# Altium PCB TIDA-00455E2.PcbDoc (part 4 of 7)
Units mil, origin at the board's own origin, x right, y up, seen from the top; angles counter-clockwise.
Board outline 6693 x 6693.1 mil, 8 copper layers (Layer 1 - Top Layer, Layer 2 - GND, Layer 3 - Sensitive, Layer 4 - GND, Layer 5 - PWR, Layer 6 - Signal, Layer 7 - GND, Layer 8 - Bottom Layer), stack 63.122 mil thick; 537 components, 407 nets, 1686 pads, 1249 vias.
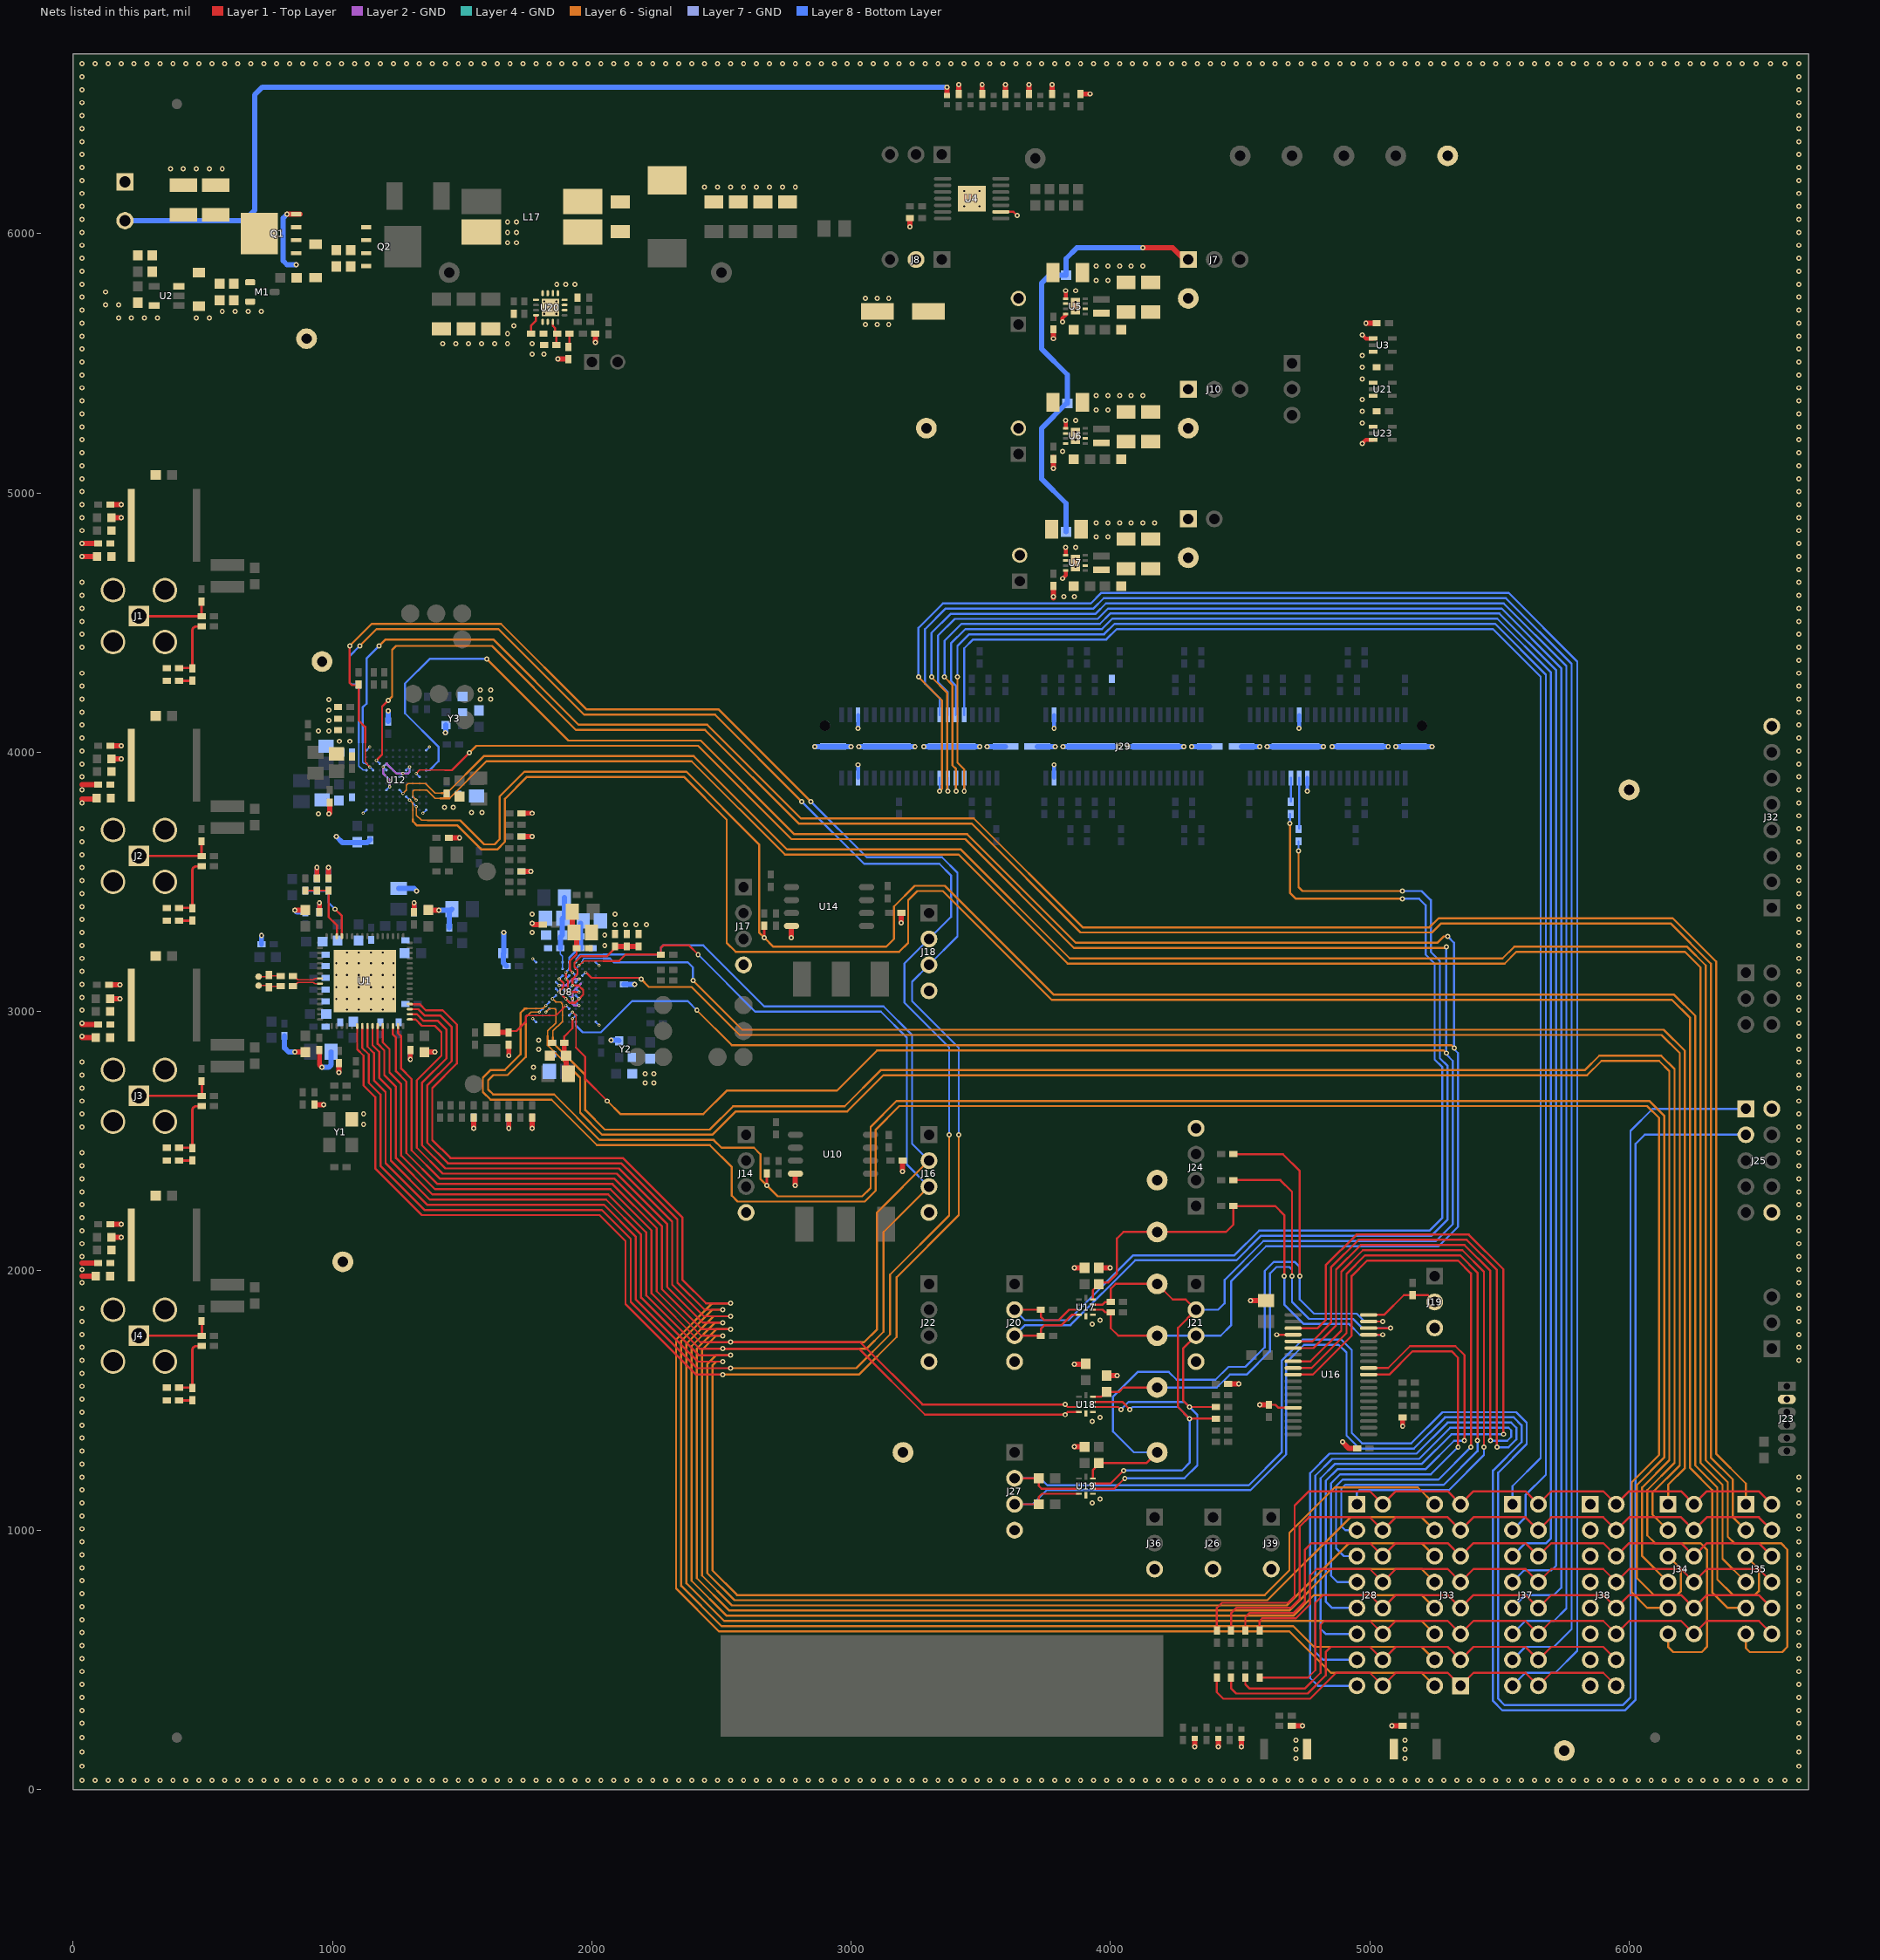
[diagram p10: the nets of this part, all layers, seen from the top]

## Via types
v1: diameter 20, hole 10, Layer 1 - Top Layer to Layer 8 - Bottom Layer, tented both sides, 1063 vias
v2: diameter 12, hole 6, Layer 1 - Top Layer to Layer 8 - Bottom Layer, tented bottom, 140 vias
v3: diameter 19.68, hole 7.87, Layer 1 - Top Layer to Layer 8 - Bottom Layer, 38 vias
v4: diameter 19.68, hole 7.87, Layer 1 - Top Layer to Layer 8 - Bottom Layer, tented top, 4 vias
v5: diameter 15.75, hole 7.87, Layer 1 - Top Layer to Layer 8 - Bottom Layer, 4 vias

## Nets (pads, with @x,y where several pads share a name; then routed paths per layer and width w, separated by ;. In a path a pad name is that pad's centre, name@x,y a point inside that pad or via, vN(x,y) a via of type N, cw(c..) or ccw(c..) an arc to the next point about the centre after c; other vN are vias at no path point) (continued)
GND: C1.2 C2.2 C3.2 C4.2 C5.2 C6.2 C7.2 C8.2 C15.2 C16.2 C17.2 C18.2 C19.2 C20.2 C21.2 C22.2 C30.1 C31.1 C32.2 C34.2 C35.2 C36.2 C37.2 C38.2 C39.2 C40.2 C41.2 C42.2 C43.2 C44.2 C45.2 C46.2 C47.2 C48.2 C49.2 C50.2 C51.2 C52.2 C53.2 C54.2 C56.2 C57.2 C58.2 C60.2 C61.2 C62.2 C63.2 C64.2 C65.2 C66.2 C69.2 C70.2 C71.2 C72.2 C75.2 C76.2 C77.2 C80.2 C84.2 C85.2 C86.2 C90.2 C91.2 C92.2 C94.2 C95.2 C96.2 C97.2 C100.2 C101.2 C102.2 C103.2 C106.2 C107.2 C108.2 C111.2 C112.2 C113.2 C114.2 C115.2 C116.2 C117.2 C118.1 C119.1 C120.1 C121.1 C122.1 C123.1 C124.1 C125.2 C126.2 C127.1 C128.2 C129.2 C130.2 C131.2 C132.1 C133.1 C134.2 C135.2 C136.2 C137.2 C138.1 C139.1 C140.1 C141.1 C142.1 C143.1 C144.1 C145.2 C146.2 C147.1 C148.2 C149.2 C150.2 C151.2 C152.1 C153.1 C154.2 C155.2 C156.2 C157.2 C158.2 C159.2 C160.1 C161.2 C162.1 C163.2 C164.2 D2.2 D4.2 D5.2 D12.1 J1.MH1 J1.MH2 J1.MH3 J1.MH4 J2.MH1 J2.MH2 J2.MH3 J2.MH4 J3.MH1 J3.MH2 J3.MH3 J3.MH4 J4.MH1 J4.MH2 J4.MH3 J4.MH4 J5.1 J14.4 J16.4 J17.4 J18.4 J19.3 J20.4 J21.4 J22.4 J23.2 J24.4 J25.2 J25.10 J26.3 J27.4 J29.26 J29.27 J29.77 J29.78 J29.115 J29.116 J29.MP1 J29.MP2 J29.MP3 J29.MP4 J29.MP5 J29.MP6 J29.MP7 J29.MP8 J29.MP9 J29.MP10 J29.MP11 J29.MP12 J32.8 J36.3 J38.1 J38.3 J38.5 J38.7 J38.9 J38.11 J38.13 J38.15 J39.3 L17.2 M1.2 R5.1 R6.1 R7.1 R8.1 R13.1 R14.1 R15.1 R16.1 R22.2 R23.1 R25.1 R28.1 R31.2 R38.1 R41.1 R44.1 R49.1 R50.1 R54.1 R55.1 R63.1 R68.1 R75.1 R76.1 R84.1 R85.1 R93.1 R98.1 R105.1 R106.1 R114.1 R115.1 R125.1 R127.2 R129.1 R130.2 R131.1 R132.1 R133.1 R134.1 R135.1 R137.1 R138.1 R140.1 R153.1 R155.1 R158.2 R161.2 R185.1 R201.1 R204.1 S1.2 S2.2 TP8.1 TP11.1 TP13.1 TP15.1 TP43.1 TP44.1 TP45.1 TP46.1 U1.65 U2.5 U3.1 U3.3 U4.2 U4.15 U5.1 U5.4 U5.9 U6.1 U6.4 U6.9 U7.1 U7.4 U7.9 U8.A1 U8.A10 U8.D4 U8.D7 U8.E5 U8.G7 U8.K1 U8.K10 U10.4 U12.A1 U12.A10 U12.D4 U12.D7 U12.E5 U12.G7 U12.K1 U12.K10 U14.4 U16.4 U16.15 U17.5 U17.6 U18.5 U18.6 U19.5 U19.6 U20.5 U20.6 U20.10 U20.11 U20.12 U20.13 U20.14 U20.17 U21.1 U21.3 U23.1 U23.3 Y1.2 Y2.2 Y2.4 Y3.2 Y3.4 | length 8429.3
  Layer 1 - Top Layer w8: U4.2@3577.2,6083.82 3626.18,6083.82 v1(3640,6070) ; C157.2@4610,1483.62 4636.38,1483.62 4647.95,1472.05 U16.15@4704.33,1472.05 ; v1(4641.46,1753.54) U16.4@4704.33,1753.54
  Layer 1 - Top Layer w15: v1(3815,4670) 3827.6,4682.6 U7.4@3827.6,4697.4 ; v1(3815,5660) 3815,5674.8 U5.4@3827.6,5687.4 ; U7.1@3827.6,4762.6 v1(3827.6,4790) ; U6.1@3827.6,5252.6 v1(3827.6,5280) ; U5.1@3827.6,5752.6 v1(3827.6,5780) ; v1(4970,5190) 4984.41,5204.41 U23.3@5012.6,5204.41 ; v1(4970,5610) 4984.41,5595.59 U3.1@5012.6,5595.59
  Layer 1 - Top Layer w20: 35,1980 C20.2@87.44,1980 ; 35,2030 C19.2@96.38,2030 ; v1@35,2900 C16.2@87.44,2900 ; v1@35,2950 C15.2@91.38,2950 ; 35,3820 87.45,3820 C6.2@90.24,3822.8 ; 35,3875 C5.2@96.38,3875 ; v1(35,4755) C2.2@92.44,4755 ; v1(35,4805) C1.2@96.38,4805 ; C17.2@138.62,3102.5 v1(180,3102.5) ; C18.2@142.56,3050 v1(180,3050) ; C21.2@143.62,2180 v1(185,2180) ; C7.2@143.62,4025 v1(185,4025) ; C3.2@143.62,4955 v1(185,4955) ; C22.2@147.56,2130 v1(185,2130) ; C8.2@147.56,3975 v1(185,3975) ; C4.2@147.56,4905 v1(185,4905) ; v1(855,2843.5) C84.2@895,2843.5 ; v1(855,3391.5) C70.2@895,3391.5 ; R155.1@930,2641.38 v1(966.38,2641.38) ; R49.1@940,3513.62 v1(940,3555) ; C85.2@950,2851.38 950,2795 v1(960,2785) ; C71.2@950,3383.62 v1(950,3420) ; C72.2@985,3513.62 v1(985,3555) ; v1(986.24,3762.5) 990,3766.26 R106.1@990,3806.38 ; v1(1025,2765) R54.1@1025,2801.38 ; v1(1300,2815) C108.2@1300,2851.38 ; C103.2@1315,3383.62 v1(1315,3420) ; C107.2@1355,2843.5 v1(1395,2843.5) ; C101.2@1370,3391.5 v1(1410,3391.5) ; C149.2@1448.62,3670 v1(1490,3670) ; v1(1545,2550) R134.1@1545,2591.38 ; v1(1680,2550) R85.1@1680,2591.38 ; v1(1680,2830) C129.2@1680,2871.38 ; R138.1@1728.62,3540 v1(1765,3540) ; R115.1@1728.62,3675 v1(1770,3675) ; R137.1@1728.62,3765 v1(1770,3765) ; v1(1770,2550) R133.1@1770,2591.38 ; v1(1770,3340) 1775,3335 R76.1@1811.38,3335 ; v1(1870,5516.38) C43.2@1910,5516.38 ; v1(2013.62,5580) R31.2@2013.62,5615 ; v1(2769.8,3285) 2769.8,3329.49 U14.4@2770.32,3330 ; v1(2784.8,2330) 2784.8,2374.49 U10.4@2785.31,2375 ; v1(3193.62,3341.38) R93.1@3193.62,3380 ; v1(3198.62,2383.62) R63.1@3198.62,2425 ; v1(3226.38,6026.38) R140.1@3226.38,6060 ; R50.1@3415,6538.62 v1(3415,6575) ; R125.1@3505,6538.62 v1(3505,6575) ; R127.2@3595,6538.62 v1(3595,6575) ; R132.1@3685,6538.62 v1(3685,6575) ; R131.1@3775,6538.62 v1(3775,6575) ; v1@3780,4595 v1(3780,4600) R204.1@3780,4641.38 R204.1@3780,4646.38 ; v1(3780,5095) R201.1@3780,5131.38 R201.1@3780,5136.38 ; v1(3780,5595) R129.1@3780,5631.38 R129.1@3780,5636.38 ; v1(3860,1321.5) C159.2@3900,1321.5 ; v1(3860,1640) 3903.5,1640 C158.2@3905,1641.5 ; v1(3860,2011.5) C161.2@3900,2011.5 ; R130.2@3885,6538.62 v1(3921.38,6538.62) ; R135.1@3955,2011.5 v1(3998.5,2011.5) ; R153.1@3985,1596.5 v1(4025,1596.5) ; v1(4325,165) D4.2@4325,197.28 ; v1(4415,165) D5.2@4415,197.28 ; R158.2@4453.62,1565 v1(4495,1565) ; v1(4505,165) D12.1@4505,197.28 ; v1(4540,1885) C156.2@4600,1885 ; v1(4575,1483.62) C157.2@4610,1483.62 ; C155.2@4698.62,245 v1(4740,245) ; v1(4895,1340) 4920,1315 R185.1@4951.38,1315 ; v1(4985,5655) C75.2@5026.38,5655 ; v1(5085,245) C80.2@5126.38,245 ; v1(5126.38,1401.38) R161.2@5126.38,1435
  Layer 2 - GND w8: v2(1195.06,3943.68) 1195.06,3918.94 1220.65,3893.35 v2(1220.65,3866.91) ; 1208.52,3956.48 1246.91,3918.09 v2(1271.83,3918.09) 1291.09,3918.09 1297.42,3924.42 v2(1297.42,3943.68) ; v2(1874.41,3100.59) 1900,3100.59 1925.59,3126.18 v2(1951.18,3126.18) ; v2(1951.18,3023.82) 1931.92,3023.82 1925.59,3030.15 v2(1925.59,3049.41) 1925.59,3075.33 1958.5,3108.24
  Layer 7 - GND w8: 1207.85,3956.48 v2(1195.06,3943.68) 1195.06,3918.94 1220.65,3893.35 v2(1220.65,3866.91) ; 1208.52,3956.48 1246.91,3918.09 v2(1271.83,3918.09) 1291.09,3918.09 1297.42,3924.42 v2(1297.42,3943.68) ; v2(1874.41,3100.59) 1900,3100.59 1925.59,3126.18 v2(1951.18,3126.18) v2@1953.82,3126.18 ; v2(1951.18,3023.82) 1931.92,3023.82 1925.59,3030.15 v2(1925.59,3049.41) 1925.59,3075.33 1958.5,3108.24
  Layer 4 - GND w8: v2(1195.06,3943.68) 1195.06,3918.94 1220.65,3893.35 v2(1220.65,3866.91) ; 1208.52,3956.48 1246.91,3918.09 v2(1271.83,3918.09) 1291.09,3918.09 1297.42,3924.42 v2(1297.42,3943.68) ; v2(1874.41,3100.59) 1900,3100.59 1925.59,3126.18 v2(1951.18,3126.18) ; v2(1951.18,3023.82) 1931.92,3023.82 1925.59,3030.15 v2(1925.59,3049.41) 1925.59,3075.33 1958.5,3108.24
  Layer 8 - Bottom Layer w5: v2(1118.29,3764.55) U12.K10@1131.08,3777.34 ; U12.A10@1131.08,4007.66 v2(1143.88,4020.45) ; v2(1195.06,3943.68) U12.D7@1207.85,3930.89 ; U12.G7@1207.85,3854.11 v2(1220.65,3866.91) ; U12.E5@1259.04,3905.3 v2(1271.83,3918.09) ; U12.D4@1284.63,3930.89 v2(1297.42,3943.68) ; v2(1348.6,3764.55) U12.K1@1361.4,3777.34 ; U12.A1@1361.4,4007.66 v2(1374.19,4020.45) ; v2(1772.05,2972.64) U8.K1@1784.84,2959.84 ; v2(1772.05,3202.95) U8.K10@1784.84,3190.16 ; U8.G7@1861.61,3113.39 v2(1874.41,3100.59) ; U8.E5@1912.8,3062.2 v2(1925.59,3049.41) ; U8.D4@1938.39,3036.61 v2(1951.18,3023.82) ; U8.D7@1938.39,3113.39 v2(1951.18,3126.18) ; U8.A1@2015.16,2959.84 v2(2027.95,2947.05) ; U8.A10@2015.16,3190.16 v2(2027.95,3177.36)
  Layer 8 - Bottom Layer w15: J29.116@3026.56,3900.89 v1(3026.56,3951.77) ; v1(3026.56,4092.91) J29.115@3026.56,4143.8 ; J29.78@3782.47,3900.89 v1(3782.47,3951.77) ; v1(3782.47,4092.91) J29.77@3782.47,4143.8 ; v1(4727.35,4092.91) J29.27@4727.35,4143.8 ; v1(4758.85,3850) J29.26@4758.85,3900.89
  Layer 8 - Bottom Layer w20: C111.2@726.38,3260 v1(726.38,3293.62) ; C61.2@815,2906.38 815,2860 831.5,2843.5 v1(855,2843.5) ; v1(855,3391.5) 862.87,3383.62 C69.2@895,3383.62 ; R55.1@940,3513.62 v1(940,3555) ; C77.2@950,3383.62 v1(950,3420) ; v1(960,2785) 985,2785 995,2795 C60.2@995,2845 ; C86.2@985,3513.62 v1(985,3555) ; v1(1015,3675) 1039,3651 1133.37,3651 C151.2@1146.24,3663.88 ; R98.1@1215,4118.62 v1(1215,4160) ; C92.2@1255,3475 1315,3475 v1(1325,3465) ; v1(1300,2815) C106.2@1300,2851.38 ; C100.2@1315,3383.62 v1(1315,3420) ; v1(1410,3391.5) C54.2@1456.5,3391.5 ; v1(1435,4075) 1437.52,4077.52 Y3.4@1437.52,4105.39 ; C56.2@1450,3323.62 1450,3385 C54.2@1456.5,3391.5 ; C54.2@1460,3395 C54.2@1456.5,3391.5 ; v1(1545,2550) R75.1@1545,2591.38 ; v1(1660,3305) 1660,3226.5 C132.1@1658.5,3225 1658.5,3187.87 C131.2@1671.38,3175 ; v1(1680,2550) R84.1@1680,2591.38 ; R105.1@1728.62,3540 v1(1765,3540) ; R114.1@1728.62,3675 v1(1770,3675) ; v1(2075,2890) 2102.87,2890 Y2.4@2105.39,2887.48 ; R68.1@2123.62,3105 v1(2165,3105) ; v1(2860,4022.15) J29.MP12@2930.5,4022.15 v1(3000,4022.15) ; v1(3030,4022.15) J29.MP11@3137.98,4022.15 v1(3245.96,4022.15) ; v1(3280,4022.15) J29.MP10@3387.98,4022.15 v1(3495.96,4022.15) ; v1(3524.96,4022.15) J29.MP9@3595.46,4022.15 ; J29.MP8@3717.9,4022.15 v1(3787.4,4022.15) ; v1(3817.4,4022.15) J29.MP7@3925.38,4022.15 v1(4033.36,4022.15) ; v1(4067.4,4022.15) J29.MP6@4175.38,4022.15 v1(4283.36,4022.15) ; v1(4312.36,4022.15) J29.MP5@4382.86,4022.15 ; J29.MP4@4505.3,4022.15 v1(4574.8,4022.15) ; v1(4604.8,4022.15) J29.MP3@4712.78,4022.15 v1(4820.77,4022.15) ; v1(4854.8,4022.15) J29.MP2@4962.78,4022.15 v1(5070.77,4022.15) ; v1(5099.76,4022.15) J29.MP1@5170.26,4022.15 v1(5239.76,4022.15)
  other v1: 35,35 85,35 135,35 185,35 235,35 285,35 335,35 385,35 435,35 485,35 535,35 585,35 635,35 685,35 735,35 785,35 835,35 885,35 935,35 985,35 1035,35 1085,35 1135,35 1185,35 1235,35 1285,35 1335,35 1385,35 1435,35 1485,35 1535,35 1585,35 1635,35 1685,35 1735,35 1785,35 1835,35 1885,35 1935,35 1985,35 2035,35 2085,35 2135,35 2185,35 2235,35 2285,35 2335,35 2385,35 2435,35 2485,35 2535,35 2585,35 2635,35 2685,35 2735,35 2785,35 2835,35 2885,35 2935,35 2985,35 3035,35 3085,35 3135,35 3185,35 3235,35 3285,35 3335,35 3385,35 3435,35 3485,35 3535,35 3585,35 3635,35 3685,35 3735,35 3785,35 3835,35 3885,35 3935,35 3985,35 4035,35 4085,35 4135,35 4185,35 4235,35 4285,35 4335,35 4385,35 4435,35 4485,35 4535,35 4585,35 4635,35 4685,35 4735,35 4785,35 4835,35 4885,35 4935,35 4985,35 5035,35 5085,35 5135,35 5185,35 5235,35 5285,35 5335,35 5385,35 5435,35 5485,35 5535,35 5585,35 5635,35 5685,35 5735,35 5785,35 5835,35 5885,35 5935,35 5985,35 6035,35 6085,35 6135,35 6185,35 6235,35 6285,35 6335,35 6385,35 6435,35 6490,35 6545,35 6600,35 6655,35 35,90 6655,90 4715,120 5135,120 35,145 6655,145 4715,155 5135,155 4715,190 5135,190 35,200 6655,200 35,255 6655,255 35,305 6655,305 35,355 6655,355 35,405 6655,405 35,455 6655,455 35,505 6655,505 35,555 6655,555 35,605 6655,605 35,655 6655,655 35,705 6655,705 35,755 6655,755 35,805 6655,805 35,855 6655,855 35,905 6655,905 35,955 6655,955 35,1005 6655,1005 35,1055 6655,1055 35,1105 3930,1105 6655,1105 3960,1120 35,1155 6655,1155 35,1205 6655,1205 35,1255 35,1305 35,1355 35,1405 3930,1420 3960,1435 35,1455 35,1505 35,1555 35,1605 35,1655 6655,1655 35,1705 6655,1705 35,1755 6655,1755 3930,1795 35,1805 6655,1805 3960,1810 35,1855 6655,1855 6655,1905 35,1955 6655,1955 35,2005 6655,2005 35,2055 6655,2055 35,2105 6655,2105 35,2155 6655,2155 35,2205 6655,2205 35,2255 6655,2255 35,2305 6655,2305 35,2355 6655,2355 35,2405 6655,2405 35,2455 6655,2455 6655,2505 35,2555 6655,2555 1120,2565 35,2605 1120,2605 6655,2605 35,2655 6655,2655 35,2705 6655,2705 2205,2725 2240,2725 1775,2745 35,2755 6655,2755 2205,2760 2240,2760 1775,2785 35,2805 6655,2805 1795,2855 6655,2855 1795,2890 35,2905 6655,2905 35,2955 6655,2955 35,3005 6655,3005 35,3055 6655,3055 35,3105 6655,3105 35,3155 6655,3155 35,3205 6655,3205 35,3255 2050,3255 6655,3255 2050,3295 35,3305 1770,3305 6655,3305 2090,3335 2130,3335 2170,3335 2210,3335 35,3355 6655,3355 1770,3375 2090,3375 35,3405 6655,3405 35,3455 6655,3455 35,3505 6655,3505 35,3555 6655,3555 35,3605 6655,3605 35,3655 6655,3655 35,3705 6655,3705 6655,3755 946.24,3762.5 1536.24,3767.5 1576.24,3767.5 1431.24,3787.5 1466.24,3787.5 35,3805 6655,3805 35,3855 6655,3855 35,3905 6655,3905 35,3955 6655,3955 35,4005 6655,4005 1026.24,4042.5 1066.24,4042.5 35,4055 6655,4055 946.24,4082.5 986.24,4082.5 35,4105 6655,4105 986.24,4122.5 35,4155 6655,4155 986.24,4162.5 986.24,4202.5 35,4205 1570,4205 1610,4205 6655,4205 1570,4240 1610,4240 35,4255 6655,4255 35,4305 6655,4305 6655,4355 35,4405 6655,4405 35,4455 6655,4455 35,4505 6655,4505 35,4555 6655,4555 3820,4600 3860,4600 35,4605 6655,4605 35,4655 6655,4655 6655,4705 6655,4755 3865,4790 6655,4805 3945,4830 3990,4830 35,4855 6655,4855 3945,4885 3990,4885 4035,4885 4080,4885 4125,4885 4170,4885 35,4905 6655,4905 35,4955 6655,4955 35,5005 6655,5005 35,5055 6655,5055 35,5105 6655,5105 35,5155 6655,5155 3815,5160 35,5205 6655,5205 35,5255 6655,5255 4970,5270 3865,5280 35,5305 6655,5305 4970,5315 3945,5320 3990,5320 35,5355 6655,5355 4970,5360 3945,5375 3990,5375 4035,5375 4080,5375 4125,5375 35,5405 6655,5405 4970,5440 35,5455 6655,5455 4970,5485 35,5505 6655,5505 4970,5530 1770,5535 1815,5535 35,5555 6655,5555 1425,5575 1475,5575 1525,5575 1575,5575 1625,5575 1675,5575 1770,5575 35,5605 6655,5605 1675,5615 1700,5645 3055,5650 3100,5650 3145,5650 35,5655 6655,5655 175,5675 225,5675 275,5675 325,5675 475,5675 525,5675 575,5700 625,5700 675,5700 725,5700 35,5705 6655,5705 125,5725 175,5725 3055,5750 3100,5750 3145,5750 35,5755 6655,5755 125,5775 3865,5780 35,5805 1865,5805 1900,5805 1935,5805 6655,5805 3945,5820 3990,5820 35,5855 6655,5855 3945,5875 3990,5875 4035,5875 4080,5875 4125,5875 35,5905 6655,5905 35,5955 6655,5955 1675,5965 1710,5965 35,6005 1675,6005 1710,6005 6655,6005 1675,6045 1710,6045 35,6055 6655,6055 35,6105 6655,6105 35,6155 6655,6155 2435,6180 2485,6180 2535,6180 2585,6180 2635,6180 2685,6180 2735,6180 2785,6180 35,6205 6655,6205 375,6250 425,6250 475,6250 525,6250 575,6250 35,6255 6655,6255 35,6305 6655,6305 35,6355 6655,6355 35,6405 6655,6405 35,6455 6655,6455 35,6505 6655,6505 35,6555 6655,6555 35,6605 6655,6605 35,6655 85,6655 135,6655 185,6655 235,6655 285,6655 335,6655 385,6655 435,6655 485,6655 535,6655 585,6655 635,6655 685,6655 735,6655 785,6655 835,6655 885,6655 935,6655 985,6655 1035,6655 1085,6655 1135,6655 1185,6655 1235,6655 1285,6655 1335,6655 1385,6655 1435,6655 1485,6655 1535,6655 1585,6655 1635,6655 1685,6655 1735,6655 1785,6655 1835,6655 1885,6655 1935,6655 1985,6655 2035,6655 2085,6655 2135,6655 2185,6655 2235,6655 2285,6655 2335,6655 2385,6655 2435,6655 2485,6655 2535,6655 2585,6655 2635,6655 2685,6655 2735,6655 2785,6655 2835,6655 2885,6655 2935,6655 2985,6655 3035,6655 3085,6655 3135,6655 3185,6655 3235,6655 3285,6655 3335,6655 3385,6655 3435,6655 3485,6655 3535,6655 3585,6655 3635,6655 3685,6655 3735,6655 3785,6655 3835,6655 3885,6655 3935,6655 3985,6655 4035,6655 4085,6655 4135,6655 4185,6655 4235,6655 4285,6655 4335,6655 4385,6655 4435,6655 4485,6655 4535,6655 4585,6655 4635,6655 4685,6655 4735,6655 4785,6655 4835,6655 4885,6655 4935,6655 4985,6655 5035,6655 5085,6655 5135,6655 5185,6655 5235,6655 5285,6655 5335,6655 5385,6655 5435,6655 5485,6655 5535,6655 5585,6655 5635,6655 5685,6655 5735,6655 5785,6655 5835,6655 5885,6655 5935,6655 5985,6655 6035,6655 6085,6655 6135,6655 6185,6655 6235,6655 6285,6655 6335,6655 6385,6655 6435,6655 6490,6655 6545,6655 6600,6655 6655,6655
  other v3: 1055.73,3007.28 1101.91,3007.28 1148.09,3007.28 1194.27,3007.28 1014.78,3048.23 1055.73,3048.23 1101.91,3048.23 1148.09,3048.23 1194.27,3048.23 1235.22,3048.23 1014.78,3094.41 1055.73,3094.41 1101.91,3094.41 1148.09,3094.41 1194.27,3094.41 1235.22,3094.41 1014.78,3140.59 1055.73,3140.59 1101.91,3140.59 1148.09,3140.59 1194.27,3140.59 1235.22,3140.59 1014.78,3186.77 1055.73,3186.77 1101.91,3186.77 1148.09,3186.77 1194.27,3186.77 1235.22,3186.77 1055.73,3227.72 1101.91,3227.72 1148.09,3227.72 1194.27,3227.72 3865,4714.25 3865,4745.75 3865,5204.25 3865,5235.75 3865,5704.25 3865,5735.75
  other v4: 1816.38,5691.38 1863.62,5691.38 1816.38,5738.62 1863.62,5738.62
  other v5: 3435.47,6105.47 3494.53,6105.47 3435.47,6164.53 3494.53,6164.53
GPIO0: J28.2 J33.15 J34.2 J35.2 J37.2 J38.2 R104.1 | length 2845.6
  Layer 1 - Top Layer w8: R104.1@4410,613.62 4410,700 4430,720 4685,720 4710,745 4710,1095 4765,1150 5000,1150 J28.2@5050,1100 5100,1150 5300,1150 J33.15@5350,1100 5400,1150 5600,1150 J37.2@5650,1100 5700,1150 5900,1150 J38.2@5950,1100 6000,1150 6200,1150 J34.2@6250,1100 6300,1150 6500,1150 J35.2@6550,1100
GPIO0_OV1: J34.1 U8.C10 | length 6214.6
  Layer 6 - Signal w8: v1(2390,3120) 2580,2930 6133.28,2930 6215,2848.28 6215,1240 6150,1175 J34.1@6150,1100
  Layer 8 - Bottom Layer w5: U8.C10@1963.98,3190.16 1963.98,3198.98 1970,3205 2045,3205
  Layer 8 - Bottom Layer w8: 2045,3205 2070,3205 2085,3190 2370,3190 2390,3170 v1(2390,3120)
GPIO0_OV2: J35.1 U12.C10 | length 8340.9
  Layer 6 - Signal w8: v1(1180,4410) 1205,4435 1620,4435 1949,4106 2445.27,4106 2806.27,3745 3472.99,3745 3892.99,3325 5230,3325 5265,3360 6168.28,3360 6335,3193.28 6335,1295 6450,1180 J35.1@6450,1100
  Layer 8 - Bottom Layer w5: 1116.24,4037.5 1116.24,3962.5 1122.26,3956.48 U12.C10@1131.08,3956.48
  Layer 8 - Bottom Layer w8: 1116.24,4037.5 1116.24,4172.5 1131.24,4187.5 1131.24,4361.24 v1(1180,4410)
GPIO0_SOC: J29.89 J37.1 | length 5823
  Layer 8 - Bottom Layer w8: J29.89@3436.01,4143.8 3436.01,4401.01 3470,4435 3983.68,4435 4023.68,4475 5475,4475 5658.73,4291.27 5658.73,1278.73 5550,1170 J37.1@5550,1100
GPIO0_UB960: J33.16 U1.9 | length 6261.8
  Layer 1 - Top Layer w8: U1.9@1134.84,2944.27 1134.84,2865.16 1160,2840 1160,2735 1205,2690 1205,2415 1365,2255 2046.57,2255 2170,2131.57 2170,1888.73 2408.73,1650 v1(2505,1650)
  Layer 6 - Signal w8: v1(2505,1650) 2480,1650 2465,1635 2465,845 2560,750 4595,750 4690,845 4690,990 4865,1165 5185,1165 J33.16@5250,1100
GPIO0_UC: J28.1 U16.8 | length 2382.2
  Layer 1 - Top Layer w8: U16.8@4704.33,1651.18 4771.18,1651.18 4890,1770 4890,1996.57 4973.43,2080 5356.57,2080 5440,1996.57 v1(5440,1320)
  Layer 8 - Bottom Layer w8: J28.1@4950,1100 4950,1145 4960,1155 5305,1155 5440,1290 v1(5440,1320)
GPIO1: J28.4 J33.13 J34.4 J35.4 J37.4 J38.4 R119.1 | length 2696.5
  Layer 1 - Top Layer w8: R119.1@4465,613.62 4465,680 4485,700 4695,700 4730,735 4730,1015 4765,1050 5000,1050 J28.4@5050,1000 5100,1050 5300,1050 J33.13@5350,1000 5400,1050 5600,1050 J37.4@5650,1000 5700,1050 5900,1050 J38.4@5950,1000 6000,1050 6200,1050 J34.4@6250,1000 6300,1050 6500,1050 J35.4@6550,1000
GPIO1_OV1: J34.3 U8.C8 | length 6273.8
  Layer 1 - Top Layer w8: v2(1976.77,3151.77) 1998.54,3130 2185,3130 v1(2190,3125)
  Layer 6 - Signal w8: v1(2190,3125) 2220,3095 2385,3095 2570,2910 6125,2910 6195,2840 6195,1250 6090,1145 6090,1060 J34.3@6150,1000
  Layer 8 - Bottom Layer w5: U8.C8@1963.98,3138.98 v2(1976.77,3151.77)
GPIO1_OV2: J35.3 U12.C8 | length 8337.4
  Layer 1 - Top Layer w8: v2(1169.47,3969.27) 1191.24,3991.04 1191.24,4176.24 v1(1215,4200)
  Layer 6 - Signal w8: v1(1215,4200) 1230,4215 1230,4395 1245,4410 1615,4410 1939,4086 2436.98,4086 2797.98,3725 3464.71,3725 3884.71,3305 5240,3305 5275,3340 6160,3340 6315,3185 6315,1280 6400,1195 6400,1050 J35.3@6450,1000
  Layer 8 - Bottom Layer w5: v2(1169.47,3969.27) U12.C8@1182.26,3956.48
GPIO1_SOC: J29.90 J37.3 | length 6359.4
  Layer 6 - Signal w8: v1(3410,4290) 3410,3960 3436.01,3933.99 v1(3436.01,3850)
  Layer 8 - Bottom Layer w8: v1(3410,4290) 3410,4410 3455,4455 3975.39,4455 4015.39,4495 5483.28,4495 5678.73,4299.56 5678.73,1213.73 5600,1135 5600,1050 J37.3@5550,1000 ; v1(3436.01,3850) J29.90@3436.01,3900.89
GPIO1_UB960: J33.14 U1.10 | length 6222.6
  Layer 1 - Top Layer w8: U1.10@1154.53,2944.27 1154.53,2870.47 1180,2845 1180,2745 1225,2700 1225,2425 1375,2275 2054.85,2275 2190,2139.85 2190,1897.01 2412.01,1675 v1(2535,1675)
  Layer 6 - Signal w8: v1(2535,1675) 2480,1675 2445,1640 2445,835 2550,730 4605,730 4925,1050 5200,1050 J33.14@5250,1000
GPIO1_UC: J28.3 U16.9 | length 2536.5
  Layer 1 - Top Layer w8: U16.9@4704.33,1625.59 4775.59,1625.59 4910,1760 4910,1988.28 4981.72,2060 5348.28,2060 5415,1993.28 v1(5415,1345)
  Layer 8 - Bottom Layer w8: J28.3@4950,1000 4905,1000 4890,1015 4890,1160 4905,1175 5285,1175 5415,1305 v1(5415,1345)
GPIO2: J28.6 J33.11 J34.6 J35.6 J37.6 J38.6 R120.1 | length 2544.4
  Layer 1 - Top Layer w8: R120.1@4520,613.62 4520,665 4535,680 4705,680 4750,725 4750,925 4775,950 5000,950 J28.6@5050,900 5100,950 5300,950 J33.11@5350,900 5400,950 5600,950 J37.6@5650,900 5700,950 5900,950 J38.6@5950,900 6000,950 6200,950 J34.6@6250,900 6300,950 6500,950 J35.6@6550,900
GPIO2_OV1: J34.5 R62.1 U8.J3 | length 7756.8
  Layer 1 - Top Layer w10: v1(2675,2330) R62.1@2675,2376.38
  Layer 6 - Signal w5: 1745,2955 1745,2978.23 1765,2998.23 v2(1797.64,2998.23)
  Layer 6 - Signal w8: 1745,2955 1745,2825 1675,2755 1620,2755 1600,2735 1600,2700 1620,2680 1855,2680 2030,2505 2470,2505 2500,2475 2625,2475 2650,2450 2650,2355 v1(2675,2330) 2717.5,2287.5 3042.5,2287.5 3075,2320 3075,2555 3175.5,2655.5 6077.78,2655.5 6135,2598.28 6135,1280 6030,1175 6030,815 6095,750 6185,750 6200,765 6200,850 J34.5@6150,900
  Layer 8 - Bottom Layer w5: v2(1797.64,2998.23) U8.J3@1810.43,3011.02
GPIO2_OV2: J35.5 R92.1 U12.J3 | length 8700.4
  Layer 1 - Top Layer w10: v1(2665.51,3285) R92.1@2665.51,3331.38
  Layer 6 - Signal w5: v2(1323.01,3790.14) 1323.01,3757.5 1343.01,3737.5 1366.24,3737.5
  Layer 6 - Signal w8: 1366.24,3737.5 1492.5,3737.5 1585,3645 1625,3645 1645,3665 1645,3830 1740,3925 2365,3925 2645,3645 2645,3305.51 v1(2665.51,3285) 2700.51,3250 3135,3250 3165,3280 3165,3405 3245,3485 3361.57,3485 3781.57,3065 6173.28,3065 6255,2983.28 6255,1250 6340,1165 6340,810 6400,750 6485,750 6500,765 6500,850 J35.5@6450,900
  Layer 8 - Bottom Layer w5: U12.J3@1310.22,3802.93 v2(1323.01,3790.14)
GPIO2_SOC: J29.91 J37.5 | length 6239.5
  Layer 8 - Bottom Layer w8: J29.91@3404.52,4143.8 3404.52,4255.48 3385,4275 3385,4420 3440,4475 3967.11,4475 4007.11,4515 5491.57,4515 5698.73,4307.84 5698.73,968.73 5680,950 5600,950 J37.5@5550,900
GPIO2_UB960: J33.12 U1.14 | length 6130.5
  Layer 1 - Top Layer w8: U1.14@1233.27,2944.27 1233.27,2911.73 1245,2900 1245,2770 1285,2730 1285,2455 1405,2335 2079.71,2335 2250,2164.71 2250,1921.86 2421.86,1750 v1(2505,1750)
  Layer 6 - Signal w8: v1(2505,1750) 2480,1750 2425,1695 2425,825 2540,710 4680,710 4920,950 5200,950 J33.12@5250,900
GPIO2_UC: J28.5 U16.10 | length 2607.9
  Layer 1 - Top Layer w8: U16.10@4704.33,1600 4780,1600 4930,1750 4930,1980 4990,2040 5340,2040 5390,1990 v1(5390,1320)
  Layer 8 - Bottom Layer w8: J28.5@4950,900 4900,900 4870,930 4870,1170 4895,1195 5265,1195 v1(5390,1320)
GPIO3: J28.8 J33.9 J34.8 J35.8 J37.8 J38.8 R144.1 | length 2386.5
  Layer 1 - Top Layer w8: R144.1@4575,613.62 4575,650 4585,660 4715,660 4770,715 4770,825 4795,850 5000,850 J28.8@5050,800 5100,850 5300,850 J33.9@5350,800 5400,850 5600,850 J37.8@5650,800 5700,850 5900,850 J38.8@5950,800 6000,850 6200,850 J34.8@6250,800 6300,850 6500,850 J35.8@6550,800
GPIO3_OV1: J34.7 U8.H3 | length 6949.7
  Layer 6 - Signal w5: v2(1823.23,2998.23) 1836.02,3011.02 1856.98,3011.02 1861.61,3006.39 1861.61,2956.61 1830,2925 1830,2905
  Layer 6 - Signal w8: 1830,2905 1830,2870 1955,2745 1955,2610 2040,2525 2465,2525 2555,2615 2985,2615 3124,2754 5837.28,2754 5893.28,2810 6115,2810 6155,2770 6155,1270 6050,1165 6050,900 J34.7@6150,800
  Layer 8 - Bottom Layer w5: v2(1823.23,2998.23) U8.H3@1836.02,3011.02
GPIO3_OV2: J35.7 U12.H3 | length 7905
  Layer 6 - Signal w5: v2(1323.01,3815.73) 1310.22,3828.52 1310.22,3849.48 1314.85,3854.11 1364.63,3854.11 1396.24,3822.5 1416.24,3822.5
  Layer 6 - Signal w8: 1416.24,3822.5 1451.24,3822.5 1593.74,3965 2385,3965 2745,3605 3415,3605 3835,3185 5520,3185 5565,3230 6215,3230 6275,3170 6275,1260 6360,1175 6360,890 J35.7@6450,800
  Layer 8 - Bottom Layer w5: U12.H3@1310.22,3828.52 v2(1323.01,3815.73)
GPIO3_SOC: J29.92 J37.7 | length 6789.7
  Layer 6 - Signal w8: v1(3360,4290) 3390,4260 3390,3950 3404.52,3935.48 v1(3404.52,3850)
  Layer 8 - Bottom Layer w8: v1(3360,4290) 3360,4430 3425,4495 3958.82,4495 3998.82,4535 5499.85,4535 5718.73,4316.12 5718.73,863.73 5700,845 5595,845 J37.7@5550,800 ; v1(3404.52,3850) J29.92@3404.52,3900.89
GPIO3_UB960: J33.10 U1.15 | length 6188.7
  Layer 1 - Top Layer w8: U1.15@1252.95,2944.27 1252.95,2917.05 1265,2905 1265,2780 1305,2740 1305,2465 1415,2355 2087.99,2355 2270,2172.99 2270,1930.15 2425.15,1775 v1(2535,1775)
  Layer 6 - Signal w8: v1(2535,1775) 2480,1775 2405,1700 2405,815 2530,690 4690,690 4850,850 5200,850 J33.10@5250,800
GPIO3_UC: J28.7 U16.29 | length 1750.3
  Layer 1 - Top Layer w8: U16.29@4995.67,1600 5075,1600 5165,1690 5315,1690 5340,1665 v1(5340,1320)
  Layer 8 - Bottom Layer w8: J28.7@4950,800 4875,800 4850,825 4850,1180 4885,1215 5235,1215 v1(5340,1320)
GPIO4: J28.10 J33.7 J34.10 J35.10 J37.10 J38.10 R146.1 | length 2487.1
  Layer 1 - Top Layer w8: R146.1@4575,431.38 4761.38,431.38 4790,460 4790,720 4820,750 5000,750 J28.10@5050,700 5100,750 5300,750 J33.7@5350,700 5400,750 5600,750 J37.10@5650,700 5700,750 5900,750 J38.10@5950,700 6000,750 6200,750 J34.10@6250,700 6300,750 6500,750 J35.10@6550,700
GPIO4_OV1: J34.9 U8.H4 | length 7647.3
  Layer 6 - Signal w5: 1750,3011.02 1810.43,3011.02 v2(1823.23,3023.82)
  Layer 6 - Signal w8: 1750,3011.02 1741.02,3011.02 1725,2995 1725,2835 1665,2775 1610,2775 1580,2745 1580,2690 1610,2660 1845,2660 2020,2485 2455,2485 2540,2400 2540,2290 2562.5,2267.5 3052.5,2267.5 3095,2310 3095,2545 3185.5,2635.5 6069.5,2635.5 6115,2590 6115,1290 6010,1185 6010,760 6070,700 J34.9@6150,700
  Layer 8 - Bottom Layer w5: v2(1823.23,3023.82) U8.H4@1836.02,3036.61
GPIO4_OV2: J35.9 U12.H4 | length 8647.8
  Layer 6 - Signal w5: v2(1297.42,3815.73) 1310.22,3802.93 1310.22,3742.5
  Layer 6 - Signal w8: 1310.22,3742.5 1310.22,3733.52 1326.24,3717.5 1482.5,3717.5 1575,3625 1635,3625 1665,3655 1665,3820 1750,3905 2355,3905 2520,3740 2520,3265 2555,3230 3185,3230 3220,3265 3220,3430 3255,3465 3353.28,3465 3773.28,3045 6165,3045 6235,2975 6235,1240 6320,1155 6320,760 6380,700 J35.9@6450,700
  Layer 8 - Bottom Layer w5: U12.H4@1284.63,3828.52 v2(1297.42,3815.73)
GPIO4_SOC: J29.93 J37.9 | length 6629.9
  Layer 8 - Bottom Layer w8: J29.93@3373.02,4143.8 3373.02,4231.98 3335,4270 3335,4450 3399.27,4514.27 3950.84,4514.27 3990.84,4554.27 5507.84,4554.27 5738,4324.11 5738,778 5710,750 5600,750 J37.9@5550,700
GPIO4_UB960: J33.8 U1.17 | length 6265.7
  Layer 1 - Top Layer w8: U1.17@1298.23,2969.86 1320.14,2969.86 1345,2945 1395,2945 1420,2920 1420,2830 1325,2735 1325,2475 1425,2375 2096.27,2375 2290,2181.27 2290,1938.43 2428.43,1800 v1(2505,1800)
  Layer 6 - Signal w8: v1(2505,1800) 2475,1800 2385,1710 2385,805 2520,670 4705,670 4785,750 5200,750 J33.8@5250,700
GPIO4_UC: J28.9 U16.30 | length 1943.4
  Layer 1 - Top Layer w8: U16.30@4995.67,1625.59 5070.59,1625.59 5155,1710 5330,1710 5365,1675 v1(5365,1345)
  Layer 8 - Bottom Layer w8: J28.9@4950,700 4855,700 4830,725 4830,1190 4875,1235 5215,1235 5325,1345 v1(5365,1345)
GPIO5: J28.12 J33.5 J34.12 J35.12 J37.12 J38.12 R148.1 | length 2506.5
  Layer 1 - Top Layer w8: R148.1@4520,431.38 4520,405 4535,390 4750,390 4810,450 4810,635 4825,650 5000,650 J28.12@5050,600 5100,650 5300,650 J33.5@5350,600 5400,650 5600,650 J37.12@5650,600 5700,650 5900,650 J38.12@5950,600 6000,650 6200,650 J34.12@6250,600 6300,650 6500,650 J35.12@6550,600
GPIO5_OV1: J34.11 U8.G5 | length 7597.4
  Layer 6 - Signal w5: v2(1848.82,3049.41) 1861.91,3036.32 1879.59,3036.32 1886.91,3029 1886.91,2961.91 1850,2925 1850,2900
  Layer 6 - Signal w8: 1850,2900 1850,2880 1975,2755 1975,2620 2050,2545 2455,2545 2545,2635 2975,2635 3114,2774 5829,2774 5885,2830 6123.28,2830 6175,2778.28 6175,1260 6070,1155 6070,980 6100,950 6275,950 6300,925 6300,550 6280,530 6170,530 6150,550 J34.11@6150,600
  Layer 8 - Bottom Layer w5: v2(1848.82,3049.41) U8.G5@1861.61,3062.2
GPIO5_OV2: J35.11 U12.G5 | length 8606.8
  Layer 6 - Signal w5: v2(1271.83,3841.32) 1284.92,3854.41 1284.92,3872.09 1292.24,3879.41 1359.33,3879.41 1396.24,3842.5 1421.24,3842.5
  Layer 6 - Signal w8: 1421.24,3842.5 1441.24,3842.5 1583.74,3985 2393.28,3985 2753.28,3625 3423.28,3625 3843.28,3205 5511.72,3205 5556.72,3250 6223.28,3250 6295,3178.28 6295,1270 6380,1185 6380,975 6405,950 6585,950 6610,925 6610,550 6590,530 6465,530 6450,545 J35.11@6450,600
  Layer 8 - Bottom Layer w5: U12.G5@1259.04,3854.11 v2(1271.83,3841.32)
GPIO5_SOC: J29.94 J37.11 | length 7165.5
  Layer 6 - Signal w8: v1(3310,4290) 3370,4230 3370,3853.02 v1(3373.02,3850)
  Layer 8 - Bottom Layer w8: v1(3310,4290) 3310,4460 3384.27,4534.27 3942.56,4534.27 3982.56,4574.27 5516.12,4574.27 5758,4332.39 5758,698 5710,650 5600,650 J37.11@5550,600 ; v1(3373.02,3850) J29.94@3373.02,3900.89
GPIO5_UB960: J33.6 U1.18 | length 6360.7
  Layer 1 - Top Layer w8: U1.18@1298.23,2989.55 1325.45,2989.55 1350,2965 1405,2965 1440,2930 1440,2820 1345,2725 1345,2485 1435,2395 2104.56,2395 2310,2189.56 2310,1946.72 2431.72,1825 v1(2535,1825)
  Layer 6 - Signal w8: v1(2535,1825) 2470,1825 2365,1720 2365,795 2510,650 5200,650 J33.6@5250,600
GPIO5_UC: J28.11 U16.3 | length 3279.4
  Layer 1 - Top Layer w8: U16.3@4704.33,1779.13 4799.13,1779.13 4830,1810 4830,2021.42 4948.58,2140 5381.42,2140 5515,2006.42 v1(5515,1370)
  Layer 8 - Bottom Layer w8: J28.11@4950,600 4830,600 4810,620 4810,1200 4865,1255 5200,1255 5315,1370 v1(5515,1370)
GPIO6: J28.14 J33.3 J37.14 J38.14 R149.1 | length 1806.9
  Layer 1 - Top Layer w8: R149.1@4465,431.38 4465,390 4485,370 4760,370 4830,440 4830,530 4850,550 5000,550 J28.14@5050,500 5100,550 5300,550 J33.3@5350,500 5400,550 5600,550 J37.14@5650,500 5700,550 5900,550 J38.14@5950,500
GPIO6_SOC: J29.95 J37.13 | length 7001.6
  Layer 8 - Bottom Layer w8: J29.95@3341.52,4143.8 3341.52,4208.48 3285,4265 3285,4475 3364.27,4554.27 3934.27,4554.27 3974.27,4594.27 5524.4,4594.27 5778,4340.68 5778,618 5710,550 5600,550 J37.13@5550,500
GPIO6_UB960: J33.4 U1.19 | length 6402
  Layer 1 - Top Layer w8: U1.19@1298.23,3009.23 1330.77,3009.23 1355,2985 1415,2985 1460,2940 1460,2810 1365,2715 1365,2495 1445,2415 2112.84,2415 2330,2197.84 2330,1955 2435,1850 v1(2505,1850)
  Layer 6 - Signal w8: v1(2505,1850) 2465,1850 2345,1730 2345,785 2500,630 4705,630 4785,550 5200,550 J33.4@5250,500
GPIO6_UC: J28.13 U16.6 | length 3547
  Layer 1 - Top Layer w8: U16.6@4704.33,1702.36 4782.36,1702.36 4870,1790 4870,2004.85 4965.15,2100 5364.85,2100 5465,1999.85 v1(5465,1345)
  Layer 8 - Bottom Layer w8: J28.13@4950,500 4820,500 4790,530 4790,1210 4855,1275 5190,1275 5310,1395 5535,1395 5545,1385 5545,1360 5530,1345 v1(5465,1345)
GPIO7: J28.16 J33.1 J37.16 J38.16 R150.1 | length 1793.1
  Layer 1 - Top Layer w8: R150.1@4410,431.38 4410,375 4435,350 4770,350 4870,450 5000,450 J28.16@5050,400 5100,450 5300,450 J33.1@5350,400 5400,450 5600,450 J37.16@5650,400 5700,450 5900,450 J38.16@5950,400
GPIO7_SOC: J29.96 J37.15 | length 7548.3
  Layer 6 - Signal w8: v1(3260,4290) 3350,4200 3350,3858.48 v1(3341.52,3850)
  Layer 8 - Bottom Layer w8: v1(3260,4290) 3260,4480 3353.54,4573.54 3923.54,4573.54 3965,4615 5535,4615 5800,4350 5800,535 5715,450 5600,450 J37.15@5550,400 ; v1(3341.52,3850) J29.96@3341.52,3900.89
GPIO7_UB960: J33.2 U1.20 | length 6558.7
  Layer 1 - Top Layer w8: U1.20@1298.23,3028.92 1336.08,3028.92 1360,3005 1425,3005 1480,2950 1480,2800 1385,2705 1385,2505 1455,2435 2120,2435 2350,2205 2350,1965 2440,1875 v1(2535,1875)
  Layer 6 - Signal w8: v1(2535,1875) 2465,1875 2325,1735 2325,775 2490,610 4690,610 4850,450 5200,450 J33.2@5250,400
GPIO7_UC: J28.15 U16.5 | length 3803.4
  Layer 1 - Top Layer w8: U16.5@4704.33,1727.95 4777.95,1727.95 4850,1800 4850,2013.14 4956.86,2120 5373.14,2120 5490,2003.14 v1(5490,1320)
  Layer 8 - Bottom Layer w8: J28.15@4950,400 4800,400 4770,430 4770,1220 4845,1295 5180,1295 5300,1415 5545,1415 5565,1395 5565,1350 5535,1320 v1(5490,1320)
HS_OPTION2: R202.1
I2C1_SCL: J29.30 R186.1 | length 91.4
  Layer 8 - Bottom Layer w8: R186.1@4695.86,3809.48 J29.30@4695.86,3900.89
I2C1_SDA: J29.28 R152.1 | length 194.9
  Layer 8 - Bottom Layer w8: R152.1@4727.35,3705.97 J29.28@4727.35,3900.89
I2C_SCL_EXT: J25.1 J27.2 R172.1 U19.3 | length 7436.5
  Layer 1 - Top Layer w8: J27.2@3630,1200 R172.1@3723.5,1200 3723.5,1170.5 3733.84,1160.16 U19.3@3878.43,1160.16
  Layer 8 - Bottom Layer w8: J27.2@3630,1200 3730,1200 3757.2,1172.8 4532.8,1172.8 4660,1300 4660,1653.72 4741.28,1735 4890,1735 4930.17,1694.83 4930.17,1374.83 4970,1335 5160,1335 5280,1455 5565,1455 5605,1415 5605,1331.72 5495,1221.72 5495,350 5520,325 5975.01,325 6005,354.99 6005,2540 6090,2625 J25.1@6450,2625
I2C_SCL_OV1: J16.2 R56.1 U1.12 U8.D10 U18.3 | length 7006.2
  Layer 1 - Top Layer w8: U1.12@1193.9,2944.27 1193.9,2881.1 1220,2855 1220,2765 1265,2720 1265,2445 1395,2315 2071.42,2315 2230,2156.42 2230,1913.58 2418.58,1725 v1(2535,1725) 3035,1725 3275,1485 v1(3825,1485) 3834.84,1475.16 U18.3@3878.43,1475.16
  Layer 6 - Signal w8: v1(2535,1725) 3050,1725 3100,1775 3100,2225 J16.2@3300,2425
  Layer 8 - Bottom Layer w5: U8.D10@1938.39,3190.16 1938.39,3203.39 1955,3220 2045,3220
  Layer 8 - Bottom Layer w8: 2045,3220 R56.1@2266.38,3220 2266.38,3246.38 2275,3255 2430,3255 2665,3020 3125,3020 3235,2910 3235,2490 J16.2@3300,2425
I2C_SCL_OV2: J18.2 R86.1 U1.8 U12.D10 | length 8305.2
  Layer 1 - Top Layer w8: U1.8@1115.16,2944.27 1115.16,2859.84 1140,2835 1140,2725 1185,2680 1185,2405 1355,2235 2038.28,2235 2150,2123.28 2150,1880.44 2405.44,1625 v1(2535,1625)
  Layer 6 - Signal w8: v1(1105,4410) 1170,4475 1640,4475 1970,4145 2475,4145 v1(2810,3810) ; v1(2535,1625) 3020,1625 3150,1755 3150,1985.36 3378,2213.36 v1(3378,2525)
  Layer 8 - Bottom Layer w5: 1101.24,4037.5 1101.24,3947.5 1117.85,3930.89 U12.D10@1131.08,3930.89
  Layer 8 - Bottom Layer w8: R86.1@1100,4261.38 1073.62,4261.38 1066.87,4268.13 1066.87,4371.87 v1(1105,4410) ; 1101.24,4037.5 R86.1@1101.24,4258.88 ; v1(2810,3810) 3050,3570 3340,3570 3385,3525 3385,3365 J18.2@3300,3280 3205,3185 3205,3035 3378,2862 v1(3378,2525)
I2C_SCL_SOC: J20.2 R121.1 R186.2 U17.3 | length 4206.1
  Layer 1 - Top Layer w8: J20.2@3630,1850 R121.1@3731.38,1850 3731.38,1823.62 3745,1810 3800,1810 3840.16,1850.16 U17.3@3878.43,1850.16
  Layer 6 - Signal w8: v1(4692,3725.62) 4692,3458 4715,3435 v1(5125,3435)
  Layer 8 - Bottom Layer w8: J20.2@3630,1850 3670,1810 3837.93,1810 4087.93,2060 4477.93,2060 4572.93,2155 5230,2155 5280,2205 5280,2785 5250,2815 5250,3185 5215,3220 5215,3410 5190,3435 v1(5125,3435) ; v1(4692,3725.62) R186.2@4692,3762
I2C_SCL_UC: J21.2 R123.1 R128.1 TP25.1 U8.E2 U12.E2 U17.8 U18.8 U19.8 | length 12455
  Layer 1 - Top Layer w5: v2(1323.01,3918.09) 1335.81,3930.89 1434.63,3930.89 ; v2(1925.59,2998.23) 1938.39,2985.43 1938.39,2861.61
  Layer 1 - Top Layer w8: 1434.63,3930.89 1460.89,3930.89 v1(1527.5,3997.5) ; 1938.39,2861.61 1975,2825 1975,2740 v1(2060,2655) ; U19.8@3931.57,1179.84 3999.84,1179.84 v1(4050,1230) ; U18.8@3931.57,1494.84 4045.16,1494.84 v1(4075,1465) ; U17.8@3931.57,1869.84 3969.84,1869.84 3980,1880 R123.1@4001.38,1880 4001.38,1931.38 4020,1950 TP25.1@4180,1950 4240,1890 4290,1890 J21.2@4330,1850 4260,1780 4260,1475 v1(4305,1430) R128.1@4406.38,1430
  Layer 6 - Signal w8: v1(1527.5,3997.5) 1555,4025 2409.85,4025 2769.85,3665 3439.85,3665 3859.85,3245 5290,3245 v1(5295,3250) ; v1(2060,2655) 2110,2605 2430,2605 2520,2695 2945,2695 3100,2850 5285,2850 v1(5295,2840)
  Layer 8 - Bottom Layer w5: v2(1323.01,3918.09) U12.E2@1335.81,3905.3 ; U8.E2@1912.8,2985.43 v2(1925.59,2998.23)
  Layer 8 - Bottom Layer w8: v1(4050,1230) 4275,1230 4305,1260 v1(4305,1430) 4260,1475 4085,1475 v1(4075,1465) ; J21.2@4330,1850 4415,1850 4440,1875 4440,1965 4590,2115 5255,2115 5320,2180 5320,2810 5295,2835 v1(5295,2840) v1(5295,3250)
I2C_SDA_EXT: J25.3 J27.3 R171.1 U19.4 | length 7388.2
  Layer 1 - Top Layer w8: J27.3@3630,1100 R171.1@3723.5,1100 3723.5,1128.5 3735.47,1140.47 U19.4@3878.43,1140.47
  Layer 8 - Bottom Layer w8: J27.3@3630,1100 3700,1100 3755,1155 4540.17,1155 4677.8,1292.63 4677.8,1646.34 4746.46,1715 4880,1715 4910,1685 4910,1365 4960,1315 5170,1315 5290,1435 5555,1435 5585,1405 5585,1340 5475,1230 5475,341.72 5511.72,305 5983.29,305 6025,346.71 6025,2490 6060,2525 J25.3@6450,2525
I2C_SDA_OV1: J16.3 R57.1 U1.11 U8.D9 U18.4 | length 7094.3
  Layer 1 - Top Layer w5: v2(1951.18,3177.36) 1968.82,3195 2045,3195
  Layer 1 - Top Layer w8: U1.11@1174.21,2944.27 1174.21,2875.79 1200,2850 1200,2755 1245,2710 1245,2435 1385,2295 2063.14,2295 2210,2148.14 2210,1905.29 2415.29,1700 v1(2505,1700) 3030,1700 3284.37,1445.63 v1(3825,1445.63) 3834.84,1455.47 U18.4@3878.43,1455.47 ; 2045,3195 2105,3195 2130,3220 R57.1@2266.38,3220 2266.38,3246.38 2275,3255 2375,3255 v1(2410,3220)
  Layer 6 - Signal w8: v1(2505,1700) 3060,1700 3125,1765 3125,2150 J16.3@3300,2325
  Layer 8 - Bottom Layer w5: U8.D9@1938.39,3164.57 v2(1951.18,3177.36)
  Layer 8 - Bottom Layer w8: v1(2410,3220) 2630,3000 3115,3000 3215,2900 3215,2410 J16.3@3300,2325
I2C_SDA_OV2: J18.3 R87.1 U1.7 U12.D9 | length 8465
  Layer 1 - Top Layer w5: 1126.24,4037.5 1126.24,3961.32 v2(1143.88,3943.68)
  Layer 1 - Top Layer w8: v1(1066.24,4410) 1066.24,4267.5 1074.86,4258.88 1101.24,4258.88 1101.24,4122.5 1126.24,4097.5 1126.24,4037.5 ; U1.7@1095.47,2944.27 1095.47,2854.53 1120,2830 1120,2715 1165,2670 1165,2395 1345,2215 2030,2215 2130,2115 2130,1872.16 2402.16,1600 v1(2505,1600)
  Layer 6 - Signal w8: v1(1066.24,4410) 1151.24,4495 1650,4495 1980,4165 2490,4165 v1(2845,3810) ; v1(2505,1600) 3030,1600 3175,1745 3175,1975 3415,2215 v1(3415,2525)
  Layer 8 - Bottom Layer w5: v2(1143.88,3943.68) U12.D9@1156.67,3930.89
  Layer 8 - Bottom Layer w8: v1(2845,3810) 3060,3595 3350.36,3595 3410,3535.36 3410,3290 J18.3@3300,3180 3235,3115 3235,3040 3415,2860 v1(3415,2525)
I2C_SDA_SOC: J20.3 R122.1 R152.2 U17.4 | length 4118.8
  Layer 1 - Top Layer w8: J20.3@3630,1750 R122.1@3731.38,1750 3731.38,1776.38 3745,1790 3810,1790 3850.47,1830.47 U17.4@3878.43,1830.47
  Layer 6 - Signal w8: v1(4725,3620) 4725,3480 4740,3465 v1(5125,3465)
  Layer 8 - Bottom Layer w8: J20.3@3630,1750 3670.86,1790.86 3845.86,1790.86 4095.86,2040.86 4485.86,2040.86 4580.86,2135.86 5237.93,2135.86 5300,2197.93 5300,2790 5270,2820 5270,3195 5235,3230 5235,3430 5200,3465 v1(5125,3465) ; v1(4725,3620) R152.2@4725,3656.38
I2C_SDA_UC: J21.3 R124.1 R126.1 TP26.1 U8.D1 U12.D1 U17.7 U18.7 U19.7 | length 12853
  Layer 1 - Top Layer w8: U19.7@3931.57,1160.16 4015.16,1160.16 v1(4055,1200) ; U18.7@3931.57,1475.16 4029.84,1475.16 v1(4040,1465) ; U17.7@3931.57,1850.16 3969.84,1850.16 3980,1840 R124.1@4001.38,1840 4001.38,1778.62 4030,1750 TP26.1@4180,1750 ; J21.3@4330,1750 4280,1700 4280,1500 v1(4305,1475) R126.1@4406.38,1475
  Layer 6 - Signal w8: v1(1595,4360) 1910,4045 2420,4045 2781,3684 3447.72,3684 3866.72,3265 5260,3265 5285,3290 v1(5300,3290) ; v1(2405,3005) 2540,2870 5315,2870 v1(5325,2860)
  Layer 8 - Bottom Layer w8: U12.D1@1361.4,3930.89 1374.63,3930.89 1408.74,3965 1408.74,4021.26 1280,4150 1280,4265 1375,4360 v1(1595,4360) ; U8.D1@1938.39,2959.84 1938.39,2946.61 1965,2920 2035,2920 2155,3040 2370,3040 v1(2405,3005) ; v1(4040,1465) 4070,1495 4285,1495 v1(4305,1475) 4335,1445 4335,1250 4285,1200 v1(4055,1200) ; TP26.1@4180,1750 J21.3@4330,1750 4425,1750 4465,1790 4465,1960 4600,2095 5265,2095 5340,2170 5340,2840 5325,2855 v1(5325,2860) 5325,3265 v1(5300,3290)
I2C_SW_EXTERNAL: R147.1 R167.1 TP28.1 U16.37 U19.9 | length 3012.8
  Layer 1 - Top Layer w8: U19.9@3931.57,1200 3931.57,1231.57 3955,1255 R167.1@3955,1258.5 4138.5,1258.5 TP28.1@4180,1300 ; R147.1@4473.62,2450 4665,2450 4730,2385 v1(4730,1980) ; U16.37@4995.67,1804.72 v1(5050,1804.72)
  Layer 8 - Bottom Layer w8: TP28.1@4180,1300 4090,1300 4010,1380 4010,1515 4105,1610 4225,1610 4255,1580 4405,1580 4455,1630 4520,1630 4595,1705 4595,2000 4630,2035 4710,2035 4730,2015 v1(4730,1980) 4730,1890 4785,1835 4949.72,1835 4980,1804.72 v1(5050,1804.72)
I2C_SW_SOC: R135.2 R143.1 TP24.1 U16.35 U17.9 | length 1871.5
  Layer 1 - Top Layer w8: U17.9@3931.57,1889.53 3931.57,1925.08 R135.2@3955,1948.5 3961.5,1955 3990,1955 4025,1990 4025,2125 4050,2150 TP24.1@4180,2150 4445,2150 4473.62,2178.62 R143.1@4473.62,2250 4635,2250 4670,2215 v1(4670,1980) ; U16.35@4995.67,1753.54 v1(5050,1753.54)
  Layer 8 - Bottom Layer w8: v1(4670,1980) 4670,1870 4745,1795 4920,1795 4961.46,1753.54 v1(5050,1753.54)
I2C_SW_UB960: R145.1 R153.2 TP27.1 U16.36 U18.9 | length 2356.7
  Layer 1 - Top Layer w8: U18.9@3931.57,1514.53 3964.53,1514.53 3983.5,1533.5 R153.2@3985,1533.5 4033.5,1533.5 4050,1550 TP27.1@4180,1550 ; R145.1@4473.62,2350 4655,2350 4700,2305 v1(4700,1980) ; U16.36@4995.67,1779.13 v1(5080,1779.13)
  Layer 8 - Bottom Layer w8: TP27.1@4180,1550 4410,1550 4460,1600 4525,1600 4615,1690 4615,1990 4640,2015 4690,2015 4700,2005 v1(4700,1980) 4700,1880 4765,1815 4935,1815 4970.87,1779.13 v1(5080,1779.13)
IDX: C72.1 R48.1 R49.2 U1.46 | length 278.8
  Layer 1 - Top Layer w8: R48.1@895,3466.38 C72.1@985,3466.38 985,3365 1016.73,3333.27 U1.46@1016.73,3290.73
LOCAL_1V1: C52.1 C53.1 J12.1 L20.2 R43.2 TP14.1 U7.6
LOCAL_1V8: C49.1 C50.1 J10.1 L19.2 R40.2 TP12.1 U6.6
LOCAL_3V3: C45.1 C46.1 J7.1 L18.2 R36.2 R37.2 R39.1 R42.1 TP10.1 U5.6 | length 1759.1
  Layer 1 - Top Layer w20: v1(4125,5945) 4240,5945 4285,5900 J7.1@4300,5900
  Layer 8 - Bottom Layer w20: R42.1@3828.5,4850 3828.5,4960 3735,5053.5 3735,5250 3830,5345 R39.1@3833.5,5345 3833.5,5456.5 3735,5555 3735,5810 3765,5840 R36.2@3828.5,5840 3828.5,5903.5 3870,5945 v1(4125,5945)
LPTX_N: C79.1 U1.57 | length 110.5
  Layer 1 - Top Layer w5: C79.1@847.98,3097.64 851.16,3097.64 862.54,3109.02 cw(c870,3101.56) 870,3112.11 924.17,3112.11 cw(c924.17,3105.28) 929,3110.11 ccw(c934.92,3116.03) 934.92,3107.66 U1.57@951.77,3107.66
LPTX_P: C78.1 U1.56 | length 110.3
  Layer 1 - Top Layer w5: C78.1@847.98,3137.64 cw(c847.98,3129.48) 853.75,3135.25 863.36,3125.64 ccw(c870,3132.28) 870,3122.89 924.17,3122.89 ccw(c924.17,3129.72) 929,3124.89 cw(c934.92,3118.97) 934.92,3127.34 U1.56@951.77,3127.34
MODE: C86.1 R53.1 R55.2 U1.45 | length 285.6
  Layer 1 - Top Layer w8: v1(1010,3395) 1036.42,3368.58 U1.45@1036.42,3290.73
  Layer 8 - Bottom Layer w8: R53.1@896.38,3465 C86.1@985,3465 ; C86.1@985,3466.38 C86.1@985,3465 ; v1(1010,3395) 985,3420 C86.1@985,3465
MODE_UC: J19.2 R102.1 U16.38 | length 296.8
  Layer 1 - Top Layer w8: U16.38@4995.67,1830.32 5055.31,1830.32 5131.38,1906.38 R102.1@5165,1906.38 5223.62,1906.38 J19.2@5250,1880
NetC1_1: C1.1 C2.1 L1.1 L4.2 R2.2
NetC5_1: C5.1 C6.1 L2.1 L6.2 R4.2
NetC9_2: C9.2 J1.1 L7.1 | length 297.2
  Layer 1 - Top Layer w9.5: J1.1@254.13,4525 C9.2@496.38,4525 ; C9.2@495,4526.38 L7.1@495,4581.38
NetC10_2: C10.2 J2.1 L8.1 | length 299.2
  Layer 1 - Top Layer w9.5: J2.1@254.13,3600 C10.2@496.38,3600 495,3601.38 L8.1@495,3656.38
NetC11_1: C11.1 C13.2 R5.2 | length 242.7
  Layer 1 - Top Layer w9.5: R5.2@408.62,4325 C13.2@460,4325 ; C13.2@460,4323.62 C13.2@460,4325 ; C11.1@496.38,4485 475,4485 ccw(c475,4470) 460,4470 C13.2@460,4325
NetC12_1: C12.1 C14.2 R6.2 | length 242.7
  Layer 1 - Top Layer w9.5: R6.2@408.62,3400 C14.2@460,3400 ; C14.2@460,3398.62 C14.2@460,3400 ; C12.1@496.38,3560 475,3560 ccw(c475,3545) 460,3545 C14.2@460,3400
NetC13_1: C13.1 R7.2 | length 52.2
  Layer 1 - Top Layer w9.5: R7.2@408.62,4275 458.62,4275 ccw(c458.62,4276.38) C13.1@460,4276.38
NetC14_1: C14.1 R8.2 | length 52.2
  Layer 1 - Top Layer w9.5: R8.2@408.62,3350 458.62,3350 ccw(c458.62,3351.38) C14.1@460,3351.38
NetC15_1: C15.1 C16.1 L9.1 L12.2 R10.2
NetC19_1: C19.1 C20.1 L10.1 L14.2 R12.2
NetC23_2: C23.2 J3.1 L15.1 | length 299.2
  Layer 1 - Top Layer w9.5: J3.1@254.13,2675 C23.2@496.38,2675 496.38,2730 L15.1@495,2731.38
NetC24_2: C24.2 J4.1 L16.1 | length 299.4
  Layer 1 - Top Layer w9.5: J4.1@254.13,1750 C24.2@496.38,1750 496.38,1805 ccw(c495,1805) L16.1@495,1806.38
NetC25_1: C25.1 C27.2 R13.2 | length 242.7
  Layer 1 - Top Layer w9.5: R13.2@408.62,2475 C27.2@460,2475 ; C27.2@460,2473.62 C27.2@460,2475 ; C25.1@496.38,2635 475,2635 ccw(c475,2620) 460,2620 C27.2@460,2475
NetC26_1: C26.1 C28.2 R14.2 | length 242.7
  Layer 1 - Top Layer w9.5: R14.2@408.62,1550 C28.2@460,1550 ; C28.2@460,1548.62 C28.2@460,1550 ; C26.1@496.38,1710 475,1710 ccw(c475,1695) 460,1695 C28.2@460,1550
NetC27_1: C27.1 R15.2 | length 52.2
  Layer 1 - Top Layer w9.5: R15.2@408.62,2425 458.62,2425 ccw(c458.62,2426.38) C27.1@460,2426.38
NetC28_1: C28.1 R16.2 | length 52.2
  Layer 1 - Top Layer w9.5: R16.2@408.62,1500 458.62,1500 ccw(c458.62,1501.38) C28.1@460,1501.38
NetC29_1: C29.1 D1.1 Q1.1 Q1.2 Q1.3 Q2.1 Q2.2 Q2.3 R18.1
NetC29_2: C29.2 D1.2 Q1.4 Q2.4 R18.2 R19.2 | length 292.4
  Layer 1 - Top Layer w20: v1(825,6075) Q1.4@860.43,6075 Q1.4@875,6075
  Layer 8 - Bottom Layer w20: v1(825,6075) 810,6060 810,5895 825,5880 v1(860,5880)
NetC30_2: C30.2 C31.2 D6.1 J5.2 Q1.5 R20.2 R21.2 | length 3674
  Layer 1 - Top Layer w20: D6.1@3370,6535 v1(3370,6565)
  Layer 8 - Bottom Layer w20: J5.2@200,6050 660,6050 700,6090 700,6535 730,6565 v1(3370,6565)
NetC32_1: C32.1 D2.1 M1.1 R20.1 R22.1 U2.3
NetC33_1: C33.1 D3.2 L17.4
NetC33_2: C33.2 L17.3 U20.1 U20.15 U20.16
NetC41_1: C41.1 U20.4 | length 78.1
  Layer 1 - Top Layer w8: C41.1@1766.38,5615 1766.38,5646.38 1784.88,5664.88 U20.4@1784.88,5685.47
NetC42_1: C42.1 R27.2 U20.7 | length 86
  Layer 1 - Top Layer w8: U20.7@1849.84,5659.88 1849.84,5644.16 1858,5636 R27.2@1858,5623.38 ; C42.1@1863.62,5570 1863.62,5612.24 R27.2@1866.38,5615
NetC43_1: C43.1 R27.1 | length 52.9
  Layer 1 - Top Layer w8: C43.1@1910,5563.62 1913.62,5567.24 R27.1@1913.62,5615
NetC44_1: C44.1 C47.1 C48.1 C51.1 J8.2 J9.2 J15.2 J30.2 TP9.1 U5.2 U6.2 U7.2
NetC78_2: C78.2 R51.2 TP16.1 | length 90.1
  Layer 1 - Top Layer w5: TP16.1@715,3135 748.38,3135 R51.2@755,3141.62 758.98,3137.64 C78.2@800.74,3137.64
NetC79_2: C79.2 R51.1 TP17.1 | length 89.7
  Layer 1 - Top Layer w5: TP17.1@715,3100 749.38,3100 R51.1@755,3094.38 ; R51.1@755,3093.66 758.98,3097.64 C79.2@800.74,3097.64
NetC115_1: C115.1 C116.1 C117.1 L31.1 U8.F9 U8.F10 | length 285.8
  Layer 8 - Bottom Layer w5: C115.1@1878.62,3245 1878.62,3222.38 1887.2,3213.8 U8.F10@1887.2,3190.16 U8.F9@1887.2,3164.57
  Layer 8 - Bottom Layer w20: C115.1@1878.62,3245 1878.62,3287.13 C117.1@1886.5,3295 1886.5,3358.03 C116.1@1888.46,3360 1895,3366.54 L31.1@1895,3440
NetC118_2: C118.2 C119.2 C122.2 U8.D6 U8.E8 U8.E9 U8.E10 U8.F6 | length 404
  Layer 1 - Top Layer w8: v2(1900,3151.77) v2(1900,3126.18) 1908,3118.18 1908,3092 1900,3084 v2(1900,3075) v2(1951.18,3075)
  Layer 8 - Bottom Layer w8: U8.F6@1887.2,3087.8 v2(1900,3075) ; v2(1900,3126.18) U8.E8@1912.8,3138.98 ; v2(1900,3151.77) U8.E9@1912.8,3164.57 U8.E10@1912.8,3190.16 1912.8,3207.8 1950,3245 C122.2@1956.38,3245 ; U8.D6@1938.39,3087.8 v2(1951.18,3075)
  Layer 8 - Bottom Layer w20: C122.2@1956.38,3245 C118.2@1956.38,3290 C119.2@1956.38,3339.84
NetC120_2: C120.2 C121.2 C160.2 U8.D5 U8.E4 U8.E6 U8.F8 U8.G6 | length 722.6
  Layer 1 - Top Layer w8: v2(1874.41,3126.18) 1891,3109.59 1891,3095 1874.41,3078.41 v2(1874.41,3075) v2(1900,3049.41) 1916.41,3033 1934.77,3033 v2(1951.18,3049.41) 1967,3065.23 1967,3083 1949.41,3100.59 v2(1925.59,3100.59) 1925.59,3125.59 1945,3145 1945,3160 1933,3172 1933,3188 1959,3214 2059,3214 2090,3245 C160.2@2090,3251.38
  Layer 1 - Top Layer w20: C160.2@2090,3251.38 C120.2@2135,3251.38 C121.2@2180,3251.38
  Layer 8 - Bottom Layer w8: U8.G6@1861.61,3087.8 v2(1874.41,3075) ; v2(1874.41,3126.18) U8.F8@1887.2,3138.98 ; v2(1900,3049.41) U8.E4@1912.8,3036.61 ; U8.E6@1912.8,3087.8 v2(1925.59,3100.59) ; U8.D5@1938.39,3062.2 v2(1951.18,3049.41)
NetC123_2: C123.2 C124.2 L32.1 U8.D8 | length 273.4
  Layer 1 - Top Layer w8: v2(1925.59,3151.77) 1915,3162.36 1915,3195 1941.38,3221.38 C124.2@1941.38,3245
  Layer 1 - Top Layer w20: L32.1@1925,3385 1925,3311.54 C123.2@1931.54,3305 1941.38,3295.16 C124.2@1941.38,3245
  Layer 8 - Bottom Layer w8: v2(1925.59,3151.77) U8.D8@1938.39,3138.98
NetC129_1: C129.1 L33.1 U8.E3 | length 343.8
  Layer 1 - Top Layer w5: 1755.43,2985.43 1861.61,2985.43 v2(1900,3023.82)
  Layer 1 - Top Layer w8: C129.1@1680,2918.62 1686.38,2925 1710,2925 1745,2960 1745,2980 1750,2985 ; 1750,2985.43 1755.43,2985.43
  Layer 1 - Top Layer w20: L33.1@1630,2920 1678.62,2920 C129.1@1680,2918.62
  Layer 8 - Bottom Layer w5: v2(1900,3023.82) U8.E3@1912.8,3011.02
NetC130_1: C130.1 C133.2 R136.2 U8.D2 | length 250.8
  Layer 1 - Top Layer w8: C130.1@1893.62,2880 1893.62,2903.62 1925.59,2935.59 v2(1925.59,2972.64)
  Layer 1 - Top Layer w20: C130.1@1893.62,2880 1893.62,2837.87 C133.2@1901.5,2830 1901.5,2768.5 R136.2@1910,2760
  Layer 8 - Bottom Layer w5: v2(1925.59,2972.64) U8.D2@1938.39,2985.43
